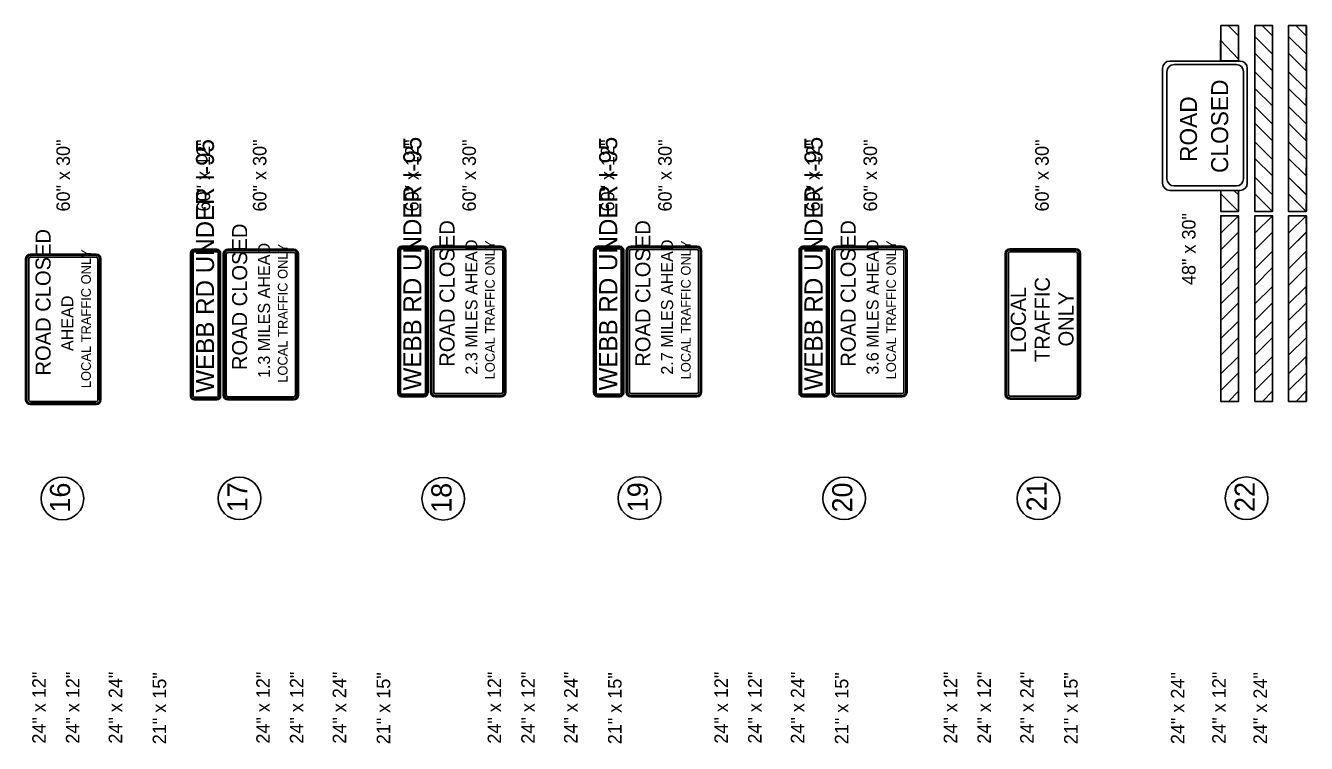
# Model space of a CAD drawing. Extents: x 1123038 to 1172987, y 554419 to 623636.
# Drawn here: x 1123803 to 1134431, y 560008 to 565969 of the extents above; entities that cross this region are included whole.
import ezdxf

# ---------------------------------------------------------------- set-up
doc = ezdxf.new("R2010")
doc.units = 0
doc.layers.add('D_Text_Standard', color=7, linetype='Continuous')
doc.layers.add('Default', color=7, linetype='Continuous')

msp = doc.modelspace()

# ---------------------------------------------------------------- linework, layer by layer
at = {"layer": 'D_Text_Standard'}
for centre in [(1124108, 562042), (1125578, 562043), (1127269, 562040), (1128897, 562045), (1130595, 562043), (1132208, 562043), (1133935, 562044)]:
    msp.add_circle(centre, 177, dxfattribs=at)
at = {"layer": 'Default'}
for p, q in [((1133720, 565679), (1133720, 565967)), ((1133722, 565969), (1133867, 565969)), ((1133869, 565682), (1133869, 565967)), ((1134003, 564427), (1134003, 565967)), ((1134004, 565969), (1134149, 565969)), ((1134151, 564427), (1134151, 565967)), ((1134283, 564427), (1134283, 565967)), ((1134284, 565969), (1134429, 565969)), ((1134431, 564427), (1134431, 565967)), ((1133297, 565674), (1133882, 565674)), ((1133333, 565645), (1133850, 565645)), ((1133238, 564659), (1133238, 565615)), ((1133274, 564696), (1133274, 565586)), ((1133909, 564696), (1133909, 565586)), ((1133941, 564659), (1133941, 565615)), ((1134149, 564564), (1134002, 564709)), ((1134429, 564564), (1134282, 564709)), ((1133297, 564600), (1133720, 564600)), ((1133333, 564637), (1133850, 564637)), ((1133720, 564600), (1133882, 564600)), ((1133720, 564427), (1133720, 564593)), ((1133867, 564564), (1133833, 564597)), ((1133869, 564427), (1133869, 564596)), ((1133867, 564425), (1133720, 564571)), ((1134149, 564425), (1134002, 564571)), ((1134429, 564425), (1134282, 564571)), ((1133867, 564390), (1133720, 564244)), ((1133720, 564388), (1133720, 562849)), ((1133722, 564425), (1133867, 564425)), ((1133722, 564390), (1133867, 564390)), ((1133869, 564388), (1133869, 562849)), ((1134149, 564390), (1134003, 564244)), ((1134003, 564388), (1134003, 562849)), ((1134004, 564425), (1134149, 564425)), ((1134005, 564390), (1134149, 564390)), ((1134151, 564388), (1134151, 562849)), ((1134429, 564390), (1134283, 564244)), ((1134283, 564388), (1134283, 562849)), ((1134284, 564425), (1134429, 564425)), ((1134285, 564390), (1134429, 564390)), ((1134431, 564388), (1134431, 562849)), ((1133867, 564252), (1133720, 564106)), ((1134149, 564252), (1134003, 564106)), ((1134429, 564252), (1134283, 564106)), ((1124389, 564071), (1123842, 564071)), ((1124389, 564061), (1123842, 564061)), ((1125171, 564080), (1125171, 562892)), ((1125179, 564080), (1125179, 562892)), ((1125192, 562892), (1125192, 564080)), ((1125390, 564111), (1125202, 564111)), ((1125390, 564103), (1125202, 564103)), ((1125202, 564090), (1125390, 564090)), ((1125400, 564080), (1125400, 562892)), ((1125413, 562892), (1125413, 564080)), ((1125421, 562892), (1125421, 564080)), ((1125442, 564072), (1125442, 562900)), ((1125452, 564072), (1125452, 562900)), ((1125468, 562900), (1125468, 564072)), ((1126028, 564111), (1125481, 564111)), ((1126028, 564101), (1125481, 564101)), ((1125481, 564085), (1126028, 564085)), ((1126041, 564072), (1126041, 562900)), ((1126057, 562900), (1126057, 564072)), ((1126067, 562900), (1126067, 564072)), ((1126892, 564105), (1126892, 562918)), ((1126900, 564105), (1126900, 562918)), ((1126913, 562918), (1126913, 564105)), ((1127110, 564136), (1126923, 564136)), ((1127110, 564129), (1126923, 564129)), ((1126923, 564116), (1127110, 564116)), ((1127121, 564105), (1127121, 562918)), ((1127134, 562918), (1127134, 564105)), ((1127142, 562918), (1127142, 564105)), ((1127163, 564097), (1127163, 562926)), ((1127173, 564097), (1127173, 562926)), ((1127189, 562926), (1127189, 564097)), ((1127749, 564136), (1127202, 564136)), ((1127749, 564126), (1127202, 564126)), ((1127202, 564110), (1127749, 564110)), ((1127762, 564097), (1127762, 562926)), ((1127777, 562926), (1127777, 564097)), ((1127788, 562926), (1127788, 564097)), ((1128516, 564105), (1128516, 562918)), ((1128524, 564105), (1128524, 562918)), ((1128537, 562918), (1128537, 564105)), ((1128735, 564136), (1128548, 564136)), ((1128735, 564129), (1128548, 564129)), ((1128548, 564116), (1128735, 564116)), ((1128746, 564105), (1128746, 562918)), ((1128759, 562918), (1128759, 564105)), ((1128766, 562918), (1128766, 564105)), ((1128787, 564097), (1128787, 562926)), ((1128798, 564097), (1128798, 562926)), ((1128813, 562926), (1128813, 564097)), ((1129373, 564136), (1128826, 564136)), ((1129373, 564126), (1128826, 564126)), ((1128826, 564110), (1129373, 564110)), ((1129386, 564097), (1129386, 562926)), ((1129402, 562926), (1129402, 564097)), ((1129412, 562926), (1129412, 564097)), ((1130221, 564105), (1130221, 562918)), ((1130229, 564105), (1130229, 562918)), ((1130242, 562918), (1130242, 564105)), ((1130439, 564136), (1130252, 564136)), ((1130439, 564129), (1130252, 564129)), ((1130252, 564116), (1130439, 564116)), ((1130450, 564105), (1130450, 562918)), ((1130463, 562918), (1130463, 564105)), ((1130471, 562918), (1130471, 564105)), ((1130492, 564097), (1130492, 562926)), ((1130502, 564097), (1130502, 562926)), ((1130518, 562926), (1130518, 564097)), ((1131078, 564136), (1130531, 564136)), ((1131078, 564126), (1130531, 564126)), ((1130531, 564110), (1131078, 564110)), ((1131091, 564097), (1131091, 562926)), ((1131106, 562926), (1131106, 564097)), ((1131117, 562926), (1131117, 564097)), ((1131932, 564077), (1131932, 562905)), ((1131942, 564077), (1131942, 562905)), ((1131958, 562905), (1131958, 564077)), ((1132518, 564116), (1131971, 564116)), ((1132518, 564105), (1131971, 564105)), ((1131971, 564090), (1132518, 564090)), ((1132531, 564077), (1132531, 562905)), ((1132546, 562905), (1132546, 564077)), ((1132557, 562905), (1132557, 564077)), ((1123803, 564032), (1123803, 562860)), ((1123813, 564032), (1123813, 562860)), ((1123829, 562860), (1123829, 564032)), ((1123842, 564045), (1124389, 564045)), ((1124402, 564032), (1124402, 562860)), ((1124417, 562860), (1124417, 564032)), ((1124428, 562860), (1124428, 564032)), ((1125390, 562882), (1125202, 562882)), ((1126028, 562887), (1125481, 562887)), ((1127110, 562907), (1126923, 562907)), ((1126923, 562894), (1127110, 562894)), ((1126923, 562886), (1127110, 562886)), ((1127749, 562913), (1127202, 562913)), ((1127202, 562897), (1127749, 562897)), ((1127202, 562886), (1127749, 562886)), ((1128735, 562907), (1128548, 562907)), ((1128548, 562894), (1128735, 562894)), ((1128548, 562886), (1128735, 562886)), ((1129373, 562913), (1128826, 562913)), ((1128826, 562897), (1129373, 562897)), ((1128826, 562886), (1129373, 562886)), ((1130439, 562907), (1130252, 562907)), ((1130252, 562894), (1130439, 562894)), ((1130252, 562886), (1130439, 562886)), ((1131078, 562913), (1130531, 562913)), ((1130531, 562897), (1131078, 562897)), ((1130531, 562886), (1131078, 562886)), ((1132518, 562892), (1131971, 562892)), ((1124389, 562847), (1123842, 562847)), ((1123842, 562832), (1124389, 562832)), ((1123842, 562821), (1124389, 562821)), ((1125202, 562869), (1125390, 562869)), ((1125202, 562861), (1125390, 562861)), ((1125481, 562871), (1126028, 562871)), ((1125481, 562861), (1126028, 562861)), ((1131971, 562876), (1132518, 562876)), ((1131971, 562866), (1132518, 562866)), ((1133722, 562847), (1133867, 562847)), ((1134005, 562847), (1134149, 562847)), ((1134285, 562847), (1134429, 562847))]:
    msp.add_line(p, q, dxfattribs=at)
for points in [[(1133867, 565883), (1133785, 565968), (1133867, 565969)], [(1134150, 565883), (1134067, 565968), (1134149, 565969)], [(1134430, 565883), (1134347, 565968), (1134429, 565969)], [(1134149, 565593), (1134151, 565730), (1134002, 565877), (1134002, 565739)], [(1134429, 565593), (1134431, 565730), (1134282, 565877), (1134282, 565739)], [(1133868, 565690), (1133719, 565847), (1133719, 565675), (1133867, 565675)], [(1134149, 565301), (1134151, 565437), (1134002, 565585), (1134002, 565447)], [(1134429, 565301), (1134431, 565437), (1134282, 565585), (1134282, 565447)], [(1134149, 565013), (1134151, 565149), (1134002, 565297), (1134002, 565159)], [(1134429, 565013), (1134431, 565149), (1134282, 565297), (1134282, 565159)], [(1134149, 564720), (1134151, 564857), (1134002, 565004), (1134002, 564866)], [(1134429, 564720), (1134431, 564857), (1134282, 565004), (1134282, 564866)], [(1134149, 564425), (1134151, 564562), (1134002, 564709), (1134002, 564571)], [(1134429, 564425), (1134431, 564562), (1134282, 564709), (1134282, 564571)], [(1133867, 564390), (1133869, 564254), (1133720, 564106), (1133720, 564244)], [(1134149, 564390), (1134151, 564254), (1134003, 564106), (1134003, 564244)], [(1134429, 564390), (1134431, 564254), (1134283, 564106), (1134283, 564244)], [(1133867, 564095), (1133869, 563959), (1133720, 563811), (1133720, 563950)], [(1134149, 564095), (1134151, 563959), (1134003, 563811), (1134003, 563950)], [(1134429, 564095), (1134431, 563959), (1134283, 563811), (1134283, 563950)], [(1133867, 563803), (1133869, 563666), (1133720, 563519), (1133720, 563657)], [(1134149, 563803), (1134151, 563666), (1134003, 563519), (1134003, 563657)], [(1134429, 563803), (1134431, 563666), (1134283, 563519), (1134283, 563657)], [(1133867, 563515), (1133869, 563379), (1133720, 563231), (1133720, 563369)], [(1134149, 563515), (1134151, 563379), (1134003, 563231), (1134003, 563369)], [(1134429, 563515), (1134431, 563379), (1134283, 563231), (1134283, 563369)], [(1133867, 563222), (1133869, 563086), (1133720, 562939), (1133720, 563077)], [(1134149, 563222), (1134151, 563086), (1134003, 562939), (1134003, 563077)], [(1134429, 563222), (1134431, 563086), (1134283, 562939), (1134283, 563077)], [(1133867, 562933), (1133785, 562847), (1133867, 562847)], [(1134150, 562933), (1134067, 562847), (1134149, 562847)], [(1134430, 562933), (1134347, 562847), (1134429, 562847)]]:
    msp.add_lwpolyline(points, close=True, dxfattribs=at)
for points in [[(1133867, 565883), (1133867, 565969), (1133785, 565968), (1133867, 565883)], [(1134150, 565883), (1134149, 565969), (1134067, 565968), (1134150, 565883)], [(1134430, 565883), (1134429, 565969), (1134347, 565968), (1134430, 565883)], [(1133868, 565682), (1133868, 565690), (1133719, 565847), (1133719, 565675), (1133867, 565675), (1133868, 565682)], [(1133720, 564600), (1133720, 564571), (1133867, 564425), (1133869, 564562), (1133830, 564600), (1133720, 564600)], [(1133833, 564596), (1133830, 564600), (1133720, 564600), (1133720, 564593), (1133720, 564593), (1133720, 564571), (1133720, 564571), (1133867, 564425), (1133867, 564427), (1133867, 564564), (1133833, 564596)], [(1133867, 562933), (1133867, 562847), (1133785, 562847), (1133867, 562933)], [(1134150, 562933), (1134149, 562847), (1134067, 562847), (1134150, 562933)], [(1134430, 562933), (1134429, 562847), (1134347, 562847), (1134430, 562933)]]:
    msp.add_lwpolyline(points, dxfattribs=at)
for centre, radius, start, end in [((1133722, 565967), 1.96, 90, 180), ((1133867, 565967), 1.96, 360, 90), ((1134004, 565967), 1.96, 90, 180), ((1134149, 565967), 1.96, 360, 90), ((1134284, 565967), 1.96, 90, 180), ((1134429, 565967), 1.96, 360, 90), ((1133297, 565615), 58.8, 90, 180), ((1133333, 565586), 58.8, 90, 180), ((1133850, 565586), 58.8, 360, 90), ((1133882, 565615), 58.8, 360, 90), ((1133333, 564696), 58.8, 180, 270), ((1133850, 564696), 58.8, 270, 360), ((1133297, 564659), 58.8, 180, 270), ((1133882, 564659), 58.8, 270, 360), ((1133722, 564427), 1.96, 180, 270), ((1133722, 564388), 1.96, 90, 180), ((1133867, 564427), 1.96, 270, 360), ((1133867, 564388), 1.96, 360, 90), ((1134004, 564427), 1.96, 180, 270), ((1134005, 564388), 1.96, 90, 180), ((1134149, 564427), 1.96, 270, 360), ((1134149, 564388), 1.96, 360, 90), ((1134284, 564427), 1.96, 180, 270), ((1134285, 564388), 1.96, 90, 180), ((1134429, 564427), 1.96, 270, 360), ((1134429, 564388), 1.96, 360, 90), ((1123842, 564032), 39.1, 90, 180), ((1123842, 564032), 28.6, 90, 180), ((1124389, 564032), 39.1, 0, 90), ((1124389, 564032), 28.6, 0, 90), ((1125202, 564080), 31.2, 90, 180), ((1125202, 564080), 23.4, 90, 180), ((1125202, 564080), 10.4, 90, 180), ((1125390, 564080), 31.2, 0, 90), ((1125390, 564080), 23.4, 0, 90), ((1125390, 564080), 10.4, 0, 90), ((1125481, 564072), 39.1, 90, 180), ((1125481, 564072), 28.6, 90, 180), ((1125481, 564072), 13, 90, 180), ((1126028, 564072), 39.1, 0, 90), ((1126028, 564072), 28.6, 0, 90), ((1126028, 564072), 13, 0, 90), ((1126923, 564105), 31.2, 90, 180), ((1126923, 564105), 23.4, 90, 180), ((1126923, 564105), 10.4, 90, 180), ((1127110, 564105), 31.2, 0, 90), ((1127110, 564105), 23.4, 0, 90), ((1127110, 564105), 10.4, 0, 90), ((1127202, 564097), 39.1, 90, 180), ((1127202, 564097), 28.6, 90, 180), ((1127202, 564097), 13, 90, 180), ((1127749, 564097), 39.1, 0, 90), ((1127749, 564097), 28.6, 0, 90), ((1127749, 564097), 13, 0, 90), ((1128548, 564105), 31.2, 90, 180), ((1128548, 564105), 23.4, 90, 180), ((1128548, 564105), 10.4, 90, 180), ((1128735, 564105), 31.2, 0, 90), ((1128735, 564105), 23.4, 0, 90), ((1128735, 564105), 10.4, 0, 90), ((1128826, 564097), 39.1, 90, 180), ((1128826, 564097), 28.6, 90, 180), ((1128826, 564097), 13, 90, 180), ((1129373, 564097), 39.1, 0, 90), ((1129373, 564097), 28.6, 0, 90), ((1129373, 564097), 13, 0, 90), ((1130252, 564105), 31.2, 90, 180), ((1130252, 564105), 23.4, 90, 180), ((1130252, 564105), 10.4, 90, 180), ((1130439, 564105), 31.2, 0, 90), ((1130439, 564105), 23.4, 0, 90), ((1130439, 564105), 10.4, 0, 90), ((1130531, 564097), 39.1, 90, 180), ((1130531, 564097), 28.6, 90, 180), ((1130531, 564097), 13, 90, 180), ((1131078, 564097), 39.1, 0, 90), ((1131078, 564097), 28.6, 0, 90), ((1131078, 564097), 13, 0, 90), ((1131971, 564077), 39.1, 90, 180), ((1131971, 564077), 28.6, 90, 180), ((1131971, 564077), 13, 90, 180), ((1132518, 564077), 39.1, 0, 90), ((1132518, 564077), 28.6, 0, 90), ((1132518, 564077), 13, 0, 90), ((1123842, 564032), 13, 90, 180), ((1124389, 564032), 13, 0, 90), ((1125202, 562892), 31.2, 180, 270), ((1125202, 562892), 23.4, 180, 270), ((1125202, 562892), 10.4, 180, 270), ((1125390, 562892), 31.2, 270, 0), ((1125390, 562892), 23.4, 270, 0), ((1125390, 562892), 10.4, 270, 0), ((1125481, 562900), 39.1, 180, 270), ((1125481, 562900), 28.6, 180, 270), ((1125481, 562900), 13, 180, 270), ((1126028, 562900), 39.1, 270, 0), ((1126028, 562900), 28.6, 270, 0), ((1126028, 562900), 13, 270, 0), ((1126923, 562918), 31.2, 180, 270), ((1126923, 562918), 23.4, 180, 270), ((1126923, 562918), 10.4, 180, 270), ((1127110, 562918), 31.2, 270, 0), ((1127110, 562918), 23.4, 270, 0), ((1127110, 562918), 10.4, 270, 0), ((1127202, 562926), 39.1, 180, 270), ((1127202, 562926), 28.6, 180, 270), ((1127202, 562926), 13, 180, 270), ((1127749, 562926), 39.1, 270, 0), ((1127749, 562926), 28.6, 270, 0), ((1127749, 562926), 13, 270, 0), ((1128548, 562918), 31.2, 180, 270), ((1128548, 562918), 23.4, 180, 270), ((1128548, 562918), 10.4, 180, 270), ((1128735, 562918), 31.2, 270, 0), ((1128735, 562918), 23.4, 270, 0), ((1128735, 562918), 10.4, 270, 0), ((1128826, 562926), 39.1, 180, 270), ((1128826, 562926), 28.6, 180, 270), ((1128826, 562926), 13, 180, 270), ((1129373, 562926), 39.1, 270, 0), ((1129373, 562926), 28.6, 270, 0), ((1129373, 562926), 13, 270, 0), ((1130252, 562918), 31.2, 180, 270), ((1130252, 562918), 23.4, 180, 270), ((1130252, 562918), 10.4, 180, 270), ((1130439, 562918), 31.2, 270, 0), ((1130439, 562918), 23.4, 270, 0), ((1130439, 562918), 10.4, 270, 0), ((1130531, 562926), 39.1, 180, 270), ((1130531, 562926), 28.6, 180, 270), ((1130531, 562926), 13, 180, 270), ((1131078, 562926), 39.1, 270, 0), ((1131078, 562926), 28.6, 270, 0), ((1131078, 562926), 13, 270, 0), ((1131971, 562905), 39.1, 180, 270), ((1131971, 562905), 28.6, 180, 270), ((1131971, 562905), 13, 180, 270), ((1132518, 562905), 39.1, 270, 0), ((1132518, 562905), 28.6, 270, 0), ((1132518, 562905), 13, 270, 0), ((1123842, 562860), 39.1, 180, 270), ((1123842, 562860), 28.6, 180, 270), ((1123842, 562860), 13, 180, 270), ((1124389, 562860), 39.1, 270, 0), ((1124389, 562860), 28.6, 270, 0), ((1124389, 562860), 13, 270, 0), ((1133722, 562849), 1.96, 180, 270), ((1133867, 562849), 1.96, 270, 360), ((1134005, 562849), 1.96, 180, 270), ((1134149, 562849), 1.96, 270, 360), ((1134285, 562849), 1.96, 180, 270), ((1134429, 562849), 1.96, 270, 360)]:
    msp.add_arc(centre, radius, start, end, dxfattribs=at)

# ---------------------------------------------------------------- texts
at = {"layer": 'D_Text_Standard'}
for s, height, p in [('60" x 30"', 112, (1124170, 564425)), ('60" x 12"', 112, (1125334, 564425)), ('60" x 30"', 112, (1125801, 564425)), ('60" x 12"', 112, (1127064, 564425)), ('60" x 30"', 112, (1127539, 564425)), ('60" x 12"', 112, (1128688, 564425)), ('60" x 30"', 112, (1129164, 564425)), ('60" x 12"', 112, (1130393, 564425)), ('60" x 30"', 112, (1130868, 564425)), ('60" x 30"', 112, (1132293, 564425)), ('48" x 30"', 112, (1133511, 563814)), ('16', 167.1, (1124172, 561925)), ('17', 167.1, (1125644, 561928)), ('18', 167.1, (1127337, 561923)), ('19', 167.1, (1128965, 561928)), ('20', 167.1, (1130663, 561926)), ('21', 167.1, (1132276, 561935)), ('22', 167.1, (1134003, 561930)), ('24" x 12"', 112, (1123970, 560006)), ('24" x 12"', 112, (1124249, 560006)), ('24" x 24"', 112, (1124604, 560006)), ('21" x 15"', 112, (1124969, 560001)), ('24" x 12"', 112, (1125829, 560006)), ('24" x 12"', 112, (1126108, 560006)), ('24" x 24"', 112, (1126463, 560006)), ('21" x 15"', 112, (1126828, 560001)), ('24" x 12"', 112, (1127749, 560006)), ('24" x 12"', 112, (1128028, 560006)), ('24" x 24"', 112, (1128383, 560006)), ('21" x 15"', 112, (1128748, 560001)), ('24" x 12"', 112, (1129631, 560006)), ('24" x 12"', 112, (1129910, 560006)), ('24" x 24"', 112, (1130265, 560006)), ('21" x 15"', 112, (1130630, 560001)), ('24" x 12"', 112, (1131534, 560006)), ('24" x 12"', 112, (1131813, 560006)), ('24" x 24"', 112, (1132168, 560006)), ('21" x 15"', 112, (1132533, 560001)), ('24" x 24"', 112, (1133419, 560002)), ('24" x 12"', 112, (1133762, 560005)), ('24" x 24"', 112, (1134104, 560002))]:
    msp.add_text(s, height=height, rotation=90, dxfattribs=at).set_placement(p)
at = {"layer": 'Default'}
for s, height, p in [('CLOSED', 141.1, (1133782, 564745)), ('ROAD', 141.1, (1133523, 564836)), ('WEBB RD UNDER I-95', 150, (1125366, 562920)), ('WEBB RD UNDER I-95', 150, (1127087, 562939)), ('WEBB RD UNDER I-95', 150, (1128712, 562939)), ('WEBB RD UNDER I-95', 150, (1130416, 562939)), ('ROAD CLOSED', 125, (1124010, 563063)), ('ROAD CLOSED', 125, (1125641, 563108)), ('ROAD CLOSED', 125, (1127362, 563136)), ('ROAD CLOSED', 125, (1128987, 563136)), ('ROAD CLOSED', 125, (1130691, 563136)), ('1.3 MILES AHEAD', 100, (1125831, 563042)), ('2.3 MILES AHEAD', 100, (1127552, 563070)), ('LOCAL TRAFFIC ONLY', 80, (1127696, 563031)), ('2.7 MILES AHEAD', 100, (1129176, 563070)), ('LOCAL TRAFFIC ONLY', 80, (1129321, 563031)), ('3.6 MILES AHEAD', 100, (1130881, 563070)), ('LOCAL TRAFFIC ONLY', 80, (1131025, 563031)), ('LOCAL TRAFFIC ONLY', 80, (1124344, 562958)), ('LOCAL TRAFFIC ONLY', 80, (1125976, 563003)), ('TRAFFIC', 125, (1132302, 563175)), ('LOCAL', 125, (1132103, 563251)), ('ONLY', 125, (1132499, 563304)), ('AHEAD', 100, (1124199, 563266))]:
    msp.add_text(s, height=height, rotation=90, dxfattribs=at).set_placement(p)

doc.saveas('drawing.dxf')
